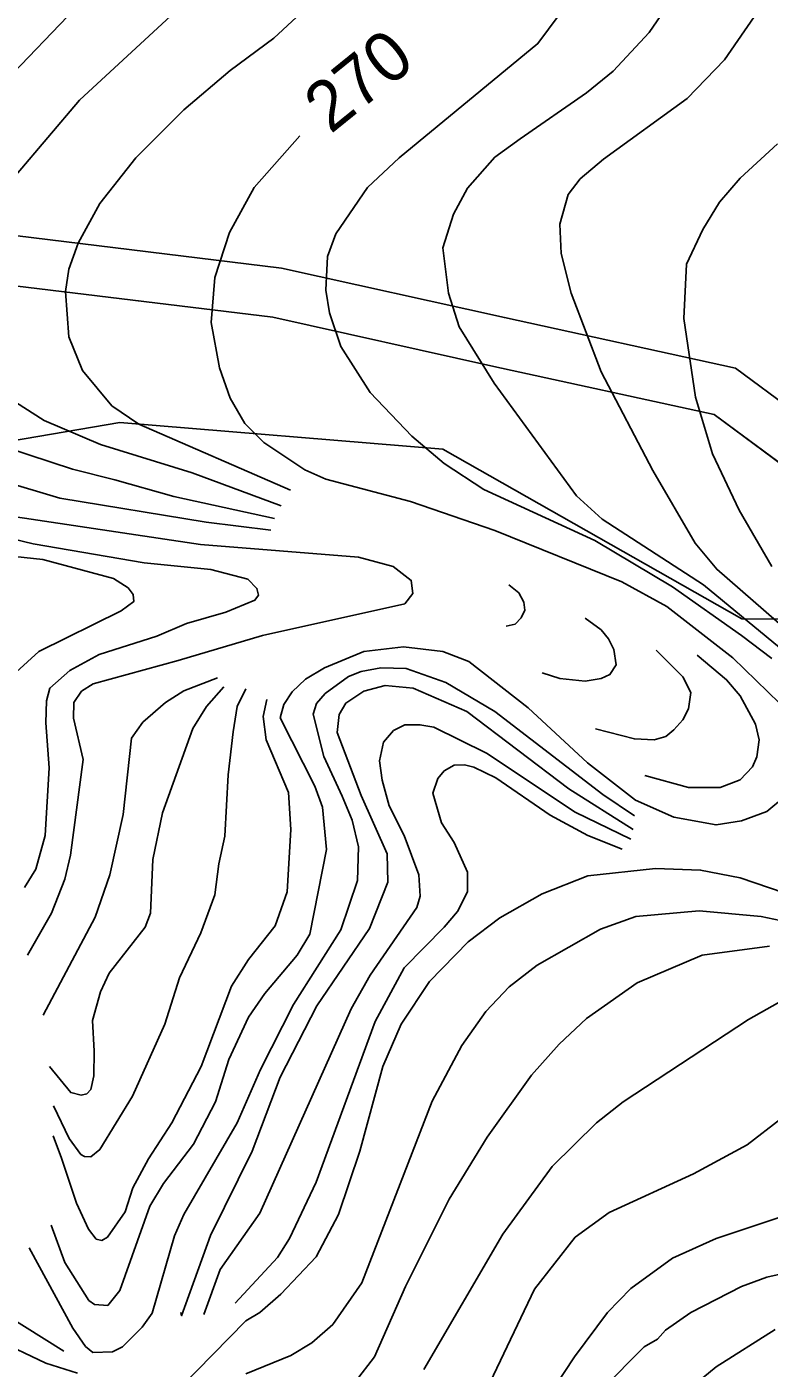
# Model space of a CAD drawing. Extents: x -555860 to -552701, y -1187050 to -1182291.
# Drawn here: x -554654.9 to -554506.2, y -1182805.2 to -1182536.6 of the extents above; entities that cross this region are included whole.
import ezdxf

# ---------------------------------------------------------------- set-up
doc = ezdxf.new("R2010")
doc.units = 0
for name, color, linetype in [('Level 28', 7, 'Continuous'), ('Level 30', 7, 'Continuous'), ('Level 40', 7, 'Continuous'), ('Level 41', 7, 'Continuous'), ('navrh_BV', 7, 'Continuous')]:
    doc.layers.add(name, color=color, linetype=linetype)

msp = doc.modelspace()

# ---------------------------------------------------------------- linework, layer by layer
at = {"layer": 'Level 28'}
msp.add_lwpolyline([(-554874.23, -1182648.75), (-554853.13, -1182640.85), (-554830.68, -1182628.91), (-554801.19, -1182601.82), (-554777.78, -1182567.93), (-554769.7, -1182563.46), (-554762.39, -1182560.36), (-554741.15, -1182562.37), (-554691.98, -1182577.49), (-554659.55, -1182588.17), (-554605.6, -1182594.73), (-554561.36, -1182604.56), (-554517.15, -1182614.23), (-554495.48, -1182630.28), (-554476.43, -1182642.32), (-554468.32, -1182642.79), (-554450.19, -1182636.98), (-554419.74, -1182644.94), (-554382.27, -1182654.75), (-554351.46, -1182662.7), (-554304.41, -1182682.05)], dxfattribs=at)
at = {"layer": 'Level 30'}
for points in [[(-554348.3, -1182653.19), (-554379.75, -1182645.07), (-554417.21, -1182635.27), (-554450.47, -1182626.57), (-554469.6, -1182632.7), (-554473.27, -1182632.49), (-554489.82, -1182622.02), (-554512.92, -1182604.92), (-554559.21, -1182594.79), (-554603.91, -1182584.86), (-554657.36, -1182578.36), (-554688.95, -1182567.96), (-554739.19, -1182552.51), (-554763.97, -1182550.17), (-554774.08, -1182554.46), (-554784.67, -1182560.32), (-554808.78, -1182595.21), (-554836.5, -1182620.68), (-554857.25, -1182631.71)], [(-554874.23, -1182648.75), (-554853.13, -1182640.85), (-554830.68, -1182628.91), (-554801.19, -1182601.82), (-554777.78, -1182567.93), (-554769.7, -1182563.46), (-554762.39, -1182560.36), (-554741.15, -1182562.37), (-554691.98, -1182577.49), (-554659.55, -1182588.17), (-554605.6, -1182594.73), (-554561.36, -1182604.56), (-554517.15, -1182614.23), (-554495.48, -1182630.28), (-554476.43, -1182642.32), (-554468.32, -1182642.79), (-554450.19, -1182636.98), (-554419.74, -1182644.94), (-554382.27, -1182654.75), (-554351.46, -1182662.7)]]:
    msp.add_lwpolyline(points, dxfattribs=at)
at = {"layer": 'Level 40'}
for points in [[(-554600.19, -1182558.4), (-554609.37, -1182568.71), (-554614.31, -1182577.74), (-554617.27, -1182586.77), (-554617.98, -1182595.8), (-554616.29, -1182604.83), (-554614.17, -1182610.9), (-554611.21, -1182615.98), (-554607.4, -1182619.79), (-554599.21, -1182625.29), (-554594.98, -1182627.13), (-554578.04, -1182631.65), (-554561.11, -1182637.43), (-554535.71, -1182647.73), (-554526.68, -1182652.67), (-554513.41, -1182662.97), (-554504.1, -1182672.01)], [(-554659.89, -1182634.33), (-554620.1, -1182640.25), (-554588.49, -1182642.79), (-554581.54, -1182644.67), (-554577.89, -1182647.45), (-554577.6, -1182650.07), (-554579.2, -1182652.11), (-554607.68, -1182658.46), (-554624.58, -1182663.5), (-554641.64, -1182668.17), (-554643.95, -1182669.61), (-554645.5, -1182671.86), (-554645.57, -1182675.03), (-554643.66, -1182683.29), (-554646.2, -1182702.49), (-554647.33, -1182707.28), (-554650.01, -1182714.06), (-554654.81, -1182722.52)], [(-554503.11, -1182690.77), (-554506.64, -1182693.74), (-554511.72, -1182695.57), (-554516.8, -1182696.42), (-554525.27, -1182694.86), (-554532.96, -1182691.48), (-554542.54, -1182683.97), (-554554.48, -1182672.99), (-554566.33, -1182663.68), (-554571.55, -1182661.7), (-554579.45, -1182660.72), (-554587.36, -1182661.7), (-554595.26, -1182664.95), (-554599.07, -1182667.21), (-554601.75, -1182669.75), (-554603.45, -1182672.29), (-554604.15, -1182674.97), (-554597.23, -1182688.66), (-554595.68, -1182692.89), (-554594.84, -1182701.36), (-554598.22, -1182718.29), (-554600.76, -1182722.52), (-554607.26, -1182730.15), (-554610.5, -1182734.94), (-554614.45, -1182743.41), (-554617.13, -1182751.88), (-554621.51, -1182760.34), (-554627.57, -1182768.25), (-554630.26, -1182772.76), (-554636.32, -1182789.7), (-554638.72, -1182792.66), (-554641.34, -1182792.49), (-554642.53, -1182791.67), (-554647.33, -1182784.05), (-554650.06, -1182776.6)], [(-554491.21, -1182714.11), (-554512, -1182707), (-554519.9, -1182705.45), (-554528.94, -1182705.17), (-554542.48, -1182706.58), (-554551.66, -1182710.25), (-554560.12, -1182715.04), (-554566.47, -1182719.84), (-554574.23, -1182727.75), (-554579.88, -1182736.35), (-554583.55, -1182744.82), (-554588.2, -1182761.75), (-554592.44, -1182774.46), (-554596.95, -1182782.92), (-554604.01, -1182790.4), (-554608.24, -1182794.07), (-554611.07, -1182795.76), (-554624.19, -1182809.17)], [(-554501.56, -1182774.17), (-554516.8, -1182779.25), (-554525.55, -1182783.2), (-554533.87, -1182789.27), (-554538.53, -1182794.07), (-554545.16, -1182802.96), (-554569.01, -1182839.09)]]:
    msp.add_lwpolyline(points, dxfattribs=at)
at = {"layer": 'Level 41'}
for points in [[(-554602.11, -1182629.35), (-554632.51, -1182616.12), (-554637.88, -1182612.45), (-554643.8, -1182605.4), (-554646.48, -1182598.62), (-554647.19, -1182589.59), (-554646.48, -1182585.08), (-554644.65, -1182579.86), (-554640.28, -1182571.95), (-554633.08, -1182562.78), (-554623.48, -1182553.18), (-554614.17, -1182545.28), (-554605.42, -1182538.79), (-554590.89, -1182525.24)], [(-554499.16, -1182664.95), (-554519.34, -1182648.3), (-554539.66, -1182635.17), (-554544.74, -1182630.52), (-554561.25, -1182607.94), (-554568.31, -1182596.65), (-554570.42, -1182589.87), (-554571.55, -1182580.84), (-554569.44, -1182574.07), (-554566.61, -1182568.85), (-554561.14, -1182562.68), (-554556.03, -1182558.97), (-554542.76, -1182549.8), (-554537.4, -1182545.42), (-554530.2, -1182537.66), (-554522.44, -1182526.37)], [(-554543.75, -1182528.07), (-554552.5, -1182539.92), (-554580.3, -1182562.78), (-554586.65, -1182568.71), (-554593, -1182578.02), (-554594.7, -1182582.54), (-554594.98, -1182589.31), (-554594.27, -1182593.83), (-554592.01, -1182600.6), (-554586.09, -1182609.77), (-554577.76, -1182618.52), (-554571.27, -1182624.02), (-554563.37, -1182629.25), (-554541.07, -1182639.41), (-554525.55, -1182648.72), (-554511.72, -1182658.46), (-554505.65, -1182663.11)], [(-554605.32, -1182635.04), (-554625.46, -1182630.66), (-554637.31, -1182627.27), (-554645.78, -1182625.15), (-554663.56, -1182619.37), (-554671.46, -1182614.85), (-554676.97, -1182610.48), (-554680.64, -1182603.71), (-554682.33, -1182596.93), (-554682.47, -1182587.9), (-554680.64, -1182578.87), (-554678.52, -1182573.79), (-554673.58, -1182565.88), (-554660.88, -1182549.09), (-554643.66, -1182531.17)], [(-554500.81, -1182702.94), (-554481.52, -1182707), (-554474.18, -1182706.72), (-554469.24, -1182704.46), (-554466.84, -1182700.51), (-554466.98, -1182695.71), (-554468.11, -1182691.76), (-554472.21, -1182685.98), (-554481.24, -1182676.38), (-554494.79, -1182664.24), (-554516.66, -1182645.19), (-554521.01, -1182640), (-554529.5, -1182625.44), (-554539.8, -1182605.68), (-554545.87, -1182589.87), (-554547.84, -1182581.97), (-554548.13, -1182576.05), (-554546.43, -1182570.12), (-554544.03, -1182567.01), (-554539.38, -1182563.06), (-554522.58, -1182550.93), (-554515.1, -1182543.17), (-554506.5, -1182530.61)], [(-554625.18, -1182533.57), (-554644.37, -1182551.21), (-554657.07, -1182566.17), (-554663.7, -1182577.46), (-554666.52, -1182586.49), (-554667.09, -1182597.78), (-554663.98, -1182605.26), (-554660.6, -1182609.63), (-554651.42, -1182615.42), (-554640.14, -1182620.22), (-554621.79, -1182625.86), (-554603.98, -1182632.51)], [(-554664.55, -1182535.97), (-554680.21, -1182554.03), (-554689.53, -1182567.58), (-554695.31, -1182581.13), (-554697, -1182590.16), (-554697.15, -1182596.93), (-554696.16, -1182601.45), (-554690.37, -1182610.76), (-554686.14, -1182615.13), (-554681.76, -1182618.38), (-554672.03, -1182623.88), (-554648.32, -1182630.94), (-554618.97, -1182635.74), (-554606.05, -1182637.37)], [(-554504.52, -1182559.96), (-554512, -1182566.87), (-554516.09, -1182571.67), (-554519.48, -1182577.17), (-554522.72, -1182584.08), (-554523.29, -1182594.96), (-554520.89, -1182610.76), (-554517.5, -1182622.05), (-554512.14, -1182633.34), (-554505.65, -1182644.63)], [(-554674.46, -1182635.13), (-554653.68, -1182640.11), (-554631.39, -1182643.92), (-554618.02, -1182645.26), (-554610.64, -1182647.17), (-554608.82, -1182649.05), (-554608.53, -1182650.36), (-554609.23, -1182651.4), (-554615.02, -1182653.8), (-554622.92, -1182656.06), (-554628.85, -1182658.6), (-554640.42, -1182662.27), (-554646.34, -1182665.51), (-554650.3, -1182669.04), (-554650.97, -1182671.53), (-554651.14, -1182675.96), (-554650.44, -1182684.99), (-554651.28, -1182698.53), (-554653.12, -1182705.31), (-554655.38, -1182708.98)], [(-554677.39, -1182640.54), (-554651.71, -1182643.22), (-554637.59, -1182647.03), (-554634.65, -1182648.91), (-554633.64, -1182650.27), (-554633.5, -1182651.68), (-554636.04, -1182653.52), (-554652.55, -1182661.7), (-554657.07, -1182665.8)], [(-554558.87, -1182656.57), (-554557.03, -1182656.2), (-554555.89, -1182654.93), (-554555.13, -1182653.43), (-554555.32, -1182651.82), (-554556.3, -1182649.93), (-554558.34, -1182648.32)], [(-554543.05, -1182655), (-554539.83, -1182657.37), (-554538.39, -1182659.16), (-554537.26, -1182661.28), (-554536.84, -1182664.38), (-554538.08, -1182666.27), (-554539.8, -1182667.07), (-554543.05, -1182667.63), (-554548.13, -1182667.07), (-554551.66, -1182665.94)], [(-554540.99, -1182677.18), (-554533.17, -1182679.2), (-554529.22, -1182679.34), (-554526.84, -1182678.68), (-554525.27, -1182677.37), (-554523.43, -1182675.39), (-554522.3, -1182673.13), (-554521.88, -1182669.89), (-554523.43, -1182666.78), (-554528.79, -1182661.42)], [(-554520.56, -1182662.43), (-554514.68, -1182667.35), (-554512, -1182670.59), (-554508.9, -1182676.24), (-554508.19, -1182679.34), (-554508.6, -1182682.77), (-554509.48, -1182684.81), (-554512, -1182687.39), (-554515.95, -1182688.94), (-554522.3, -1182688.94), (-554531.05, -1182686.54)], [(-554654.48, -1182781.14), (-554645.71, -1182797.22), (-554643.15, -1182800.88), (-554641.68, -1182802.1), (-554637.74, -1182801.97), (-554635.76, -1182800.98), (-554631.81, -1182797.03), (-554629.83, -1182794.21), (-554625.32, -1182778.69), (-554623.48, -1182774.45), (-554612.76, -1182756.11), (-554608.1, -1182745.39), (-554601.47, -1182732.4), (-554592.01, -1182717.44), (-554588.63, -1182707.57), (-554588.49, -1182700.79), (-554589.71, -1182695.46), (-554591.75, -1182690.65), (-554595.4, -1182682.73), (-554597.52, -1182674.26), (-554596.86, -1182672.11), (-554595.11, -1182670.07), (-554590.44, -1182666.71), (-554587.92, -1182665.65), (-554583.97, -1182664.95), (-554578.89, -1182665.09), (-554570.99, -1182667.91), (-554561.11, -1182673.7), (-554539.52, -1182690.35), (-554533.12, -1182694.59)], [(-554616.72, -1182666.97), (-554623.43, -1182669.53), (-554627.15, -1182671.86), (-554631.67, -1182675.81), (-554633.93, -1182679.06), (-554635.62, -1182694.3), (-554638.3, -1182706.44), (-554641.26, -1182714.9), (-554651.68, -1182734.55)], [(-554650.4, -1182744.79), (-554646.13, -1182750.03), (-554644.06, -1182750.52), (-554642.92, -1182750.31), (-554642.1, -1182749.42), (-554641.48, -1182746.66), (-554641.46, -1182741.7), (-554641.76, -1182735.57), (-554640.14, -1182729.86), (-554638.42, -1182726.08), (-554631.24, -1182716.88), (-554630.11, -1182714.06), (-554629.69, -1182703.33), (-554627.72, -1182694.02), (-554621.65, -1182677.08), (-554618.89, -1182672.69), (-554615.44, -1182668.76)], [(-554611.03, -1182669.14), (-554612.77, -1182672.69), (-554613.59, -1182677.79), (-554614.59, -1182686.4), (-554615.24, -1182698.67), (-554616.43, -1182704.18), (-554617.27, -1182710.39), (-554620.03, -1182718.05), (-554624.33, -1182727.04), (-554627.29, -1182736.35), (-554633.78, -1182750.75), (-554640.3, -1182761.4), (-554642.11, -1182762.88), (-554643.36, -1182762.86), (-554644.09, -1182762.46), (-554646.44, -1182759.21), (-554649.59, -1182752.66)], [(-554533.41, -1182697.36), (-554546.29, -1182689.16), (-554566.75, -1182673.7), (-554577.48, -1182669.04), (-554583.12, -1182668.48), (-554587.36, -1182669.61), (-554591.03, -1182672), (-554592.34, -1182674.3), (-554592.72, -1182677.93), (-554587.92, -1182690.49), (-554582.7, -1182702.2), (-554582.56, -1182707.85), (-554586.23, -1182717.16), (-554596.81, -1182732.68), (-554604.15, -1182746.94), (-554609.8, -1182761.76), (-554618.15, -1182778.64), (-554623.93, -1182794.73), (-554624.05, -1182794.07)], [(-554649.68, -1182758.71), (-554647.95, -1182763.18), (-554644.95, -1182772.2), (-554642.56, -1182777.42), (-554641, -1182779.39), (-554639.88, -1182779.68), (-554638.75, -1182778.97), (-554635.22, -1182773.89), (-554633.66, -1182769.14), (-554630.52, -1182763.32), (-554625.9, -1182756.11), (-554619.98, -1182744.82), (-554613.88, -1182728.72), (-554610.52, -1182723.37), (-554605.16, -1182716.6), (-554602.76, -1182709.82), (-554602.02, -1182697.36), (-554602.46, -1182689.92), (-554606.99, -1182679.34), (-554607.56, -1182674.69), (-554606.85, -1182671.3)], [(-554619.47, -1182794.47), (-554616.15, -1182785.46), (-554608.24, -1182774.17), (-554589.9, -1182733.25), (-554586.09, -1182726.48), (-554576.77, -1182712.93), (-554576.07, -1182710.67), (-554576.35, -1182706.44), (-554579.31, -1182698.53), (-554582.28, -1182692.61), (-554583.73, -1182687.44), (-554584.25, -1182683.57), (-554583.44, -1182679.85), (-554581.43, -1182677.51), (-554579.17, -1182676.38), (-554576.14, -1182676.34), (-554573.39, -1182676.8), (-554562.8, -1182682.02), (-554545.02, -1182693.88), (-554533.85, -1182699.26)], [(-554535.6, -1182701.3), (-554542.48, -1182698.53), (-554550.02, -1182694.44), (-554560.97, -1182686.96), (-554565.34, -1182684.84), (-554567.24, -1182684.37), (-554569.3, -1182684.42), (-554571.27, -1182685.55), (-554572.54, -1182687.1), (-554573.53, -1182690.07), (-554571.83, -1182695.99), (-554569.29, -1182699.95), (-554566.61, -1182705.87), (-554566.61, -1182709.82), (-554568.59, -1182713.77), (-554571.3, -1182716.89), (-554579.31, -1182725.06), (-554585.1, -1182735.79), (-554596.95, -1182767.96), (-554602.32, -1182779.25), (-554604.71, -1182783.06), (-554613.18, -1182792.24)], [(-554497.61, -1182716.88), (-554507.77, -1182714.76), (-554520.19, -1182713.63), (-554532.89, -1182714.76), (-554539.94, -1182717.3), (-554552.64, -1182724.5), (-554558.29, -1182728.87), (-554562.94, -1182733.81), (-554567.74, -1182740.59), (-554573.67, -1182751.73), (-554587.78, -1182788.14), (-554593.57, -1182796.47), (-554597.8, -1182800.14), (-554602.03, -1182802.68), (-554611.07, -1182806.35)], [(-554589.05, -1182807.9), (-554585.24, -1182802.96), (-554579.03, -1182788.85), (-554570.28, -1182771.35), (-554562.66, -1182758.93), (-554553.77, -1182746.51), (-554548.27, -1182740.3), (-554542.77, -1182735.22), (-554532.6, -1182728.03), (-554519.62, -1182722.52), (-554506.07, -1182720.69)], [(-554502.97, -1182731.27), (-554510.31, -1182735.36), (-554535.43, -1182751.88), (-554540.79, -1182756.11), (-554549.68, -1182764.86), (-554559.56, -1182778.41), (-554575.36, -1182805.5)], [(-554503.82, -1182755.26), (-554510.59, -1182760.48), (-554521.32, -1182766.27), (-554538.25, -1182774.03), (-554545.02, -1182778.97), (-554553.21, -1182789.41), (-554562.1, -1182808.04)], [(-554496.48, -1182784.76), (-554506.64, -1182787.01), (-554511.72, -1182788.85), (-554521.88, -1182794.07), (-554526.96, -1182797.6), (-554528.51, -1182799.43), (-554531.19, -1182800.98), (-554539.66, -1182809.45)], [(-554741.17, -1182810.02), (-554712.1, -1182796.89), (-554704.2, -1182792.8), (-554691.22, -1182788.28), (-554681.34, -1182787.3), (-554672.94, -1182788.49), (-554667.16, -1182789.73), (-554659.36, -1182794.42), (-554647.54, -1182801.85)], [(-554726.5, -1182811.85), (-554701.1, -1182798.87), (-554694.61, -1182797.32), (-554683.32, -1182795.9), (-554668.08, -1182797.46), (-554661.3, -1182799.43), (-554651.14, -1182804.23), (-554644.79, -1182806.21)], [(-554527.38, -1182813.69), (-554516.8, -1182804.94), (-554504.95, -1182797.46)]]:
    msp.add_lwpolyline(points, dxfattribs=at)
at = {"layer": 'navrh_BV'}
for p, q in [((-554659.55, -1182588.17), (-554605.6, -1182594.73)), ((-554605.6, -1182594.73), (-554561.36, -1182604.56)), ((-554561.36, -1182604.56), (-554517.15, -1182614.23)), ((-554791.4, -1182641.99), (-554636.26, -1182615.82)), ((-554636.26, -1182615.82), (-554571.58, -1182621.17)), ((-554517.15, -1182614.23), (-554495.48, -1182630.28)), ((-554571.58, -1182621.17), (-554511.66, -1182655.13)), ((-554511.66, -1182655.13), (-554479.34, -1182655.24))]:
    msp.add_line(p, q, dxfattribs=at)

# ---------------------------------------------------------------- texts
at = {"layer": 'Level 40'}
msp.add_text('270', height=10, rotation=38.9267, dxfattribs=at).set_placement((-554594.05, -1182558.14))

doc.saveas('drawing.dxf')
